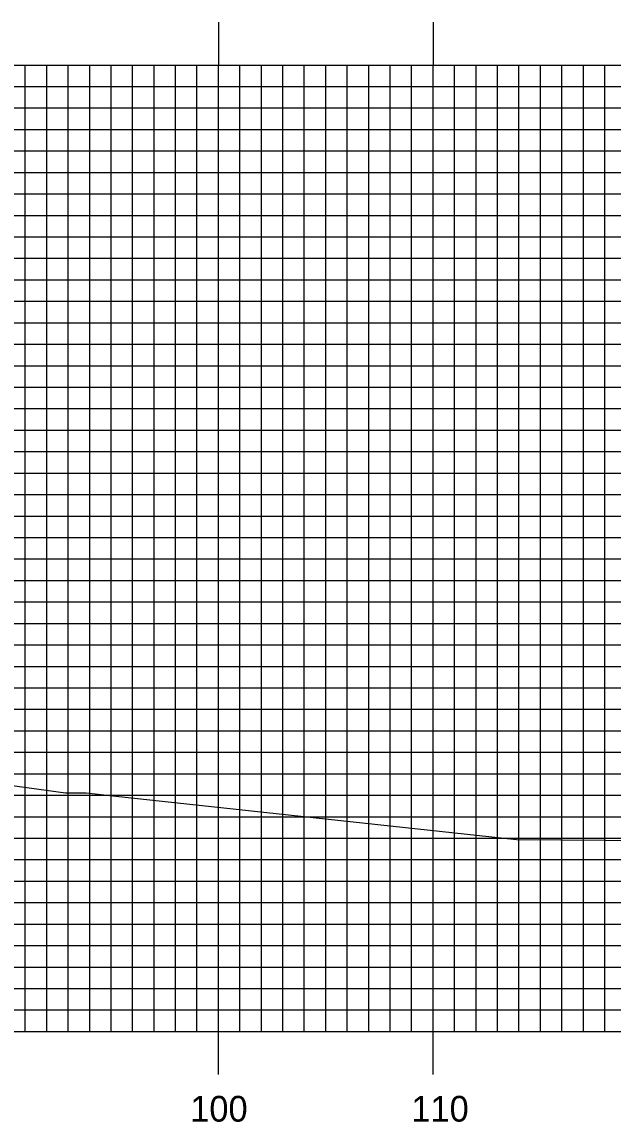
# Model space of a CAD drawing. Extents: x 1785402 to 1785745, y 442591 to 442811.
# Drawn here: x 1785658.4 to 1785685.9, y 442724.4 to 442775.7 of the extents above; entities that cross this region are included whole.
import ezdxf

# ---------------------------------------------------------------- set-up
doc = ezdxf.new("R2010")
doc.units = 0
for name, color, linetype in [('H_V ANNOTATION', 7, 'Continuous'), ('MAJOR', 7, 'Continuous'), ('MINOR', 7, 'Continuous'), ('S_Roadway_Centerline', 7, 'Continuous')]:
    doc.layers.add(name, color=color, linetype=linetype)

msp = doc.modelspace()

# ---------------------------------------------------------------- linework, layer by layer
at = {"layer": 'MAJOR'}
for p, q in [((1785667.539, 442775.669), (1785667.539, 442773.665)), ((1785677.539, 442775.669), (1785677.539, 442773.665)), ((1785427.539, 442773.665), (1785707.539, 442773.665)), ((1785427.539, 442773.665), (1785707.539, 442773.665)), ((1785667.539, 442728.665), (1785667.539, 442773.665)), ((1785677.539, 442728.665), (1785677.539, 442773.665)), ((1785427.539, 442768.665), (1785707.539, 442768.665)), ((1785427.539, 442763.665), (1785707.539, 442763.665)), ((1785427.539, 442758.665), (1785707.539, 442758.665)), ((1785427.539, 442753.665), (1785707.539, 442753.665)), ((1785427.539, 442748.665), (1785707.539, 442748.665)), ((1785427.539, 442743.665), (1785707.539, 442743.665)), ((1785427.539, 442738.665), (1785707.539, 442738.665)), ((1785427.539, 442733.665), (1785707.539, 442733.665)), ((1785427.539, 442728.665), (1785707.539, 442728.665)), ((1785427.539, 442728.665), (1785707.539, 442728.665)), ((1785667.539, 442726.661), (1785667.539, 442728.665)), ((1785677.539, 442726.661), (1785677.539, 442728.665))]:
    msp.add_line(p, q, dxfattribs=at)
at = {"layer": 'MINOR'}
for p, q in [((1785658.539, 442728.665), (1785658.539, 442773.665)), ((1785659.539, 442728.665), (1785659.539, 442773.665)), ((1785660.539, 442728.665), (1785660.539, 442773.665)), ((1785661.539, 442728.665), (1785661.539, 442773.665)), ((1785662.539, 442728.665), (1785662.539, 442773.665)), ((1785663.539, 442728.665), (1785663.539, 442773.665)), ((1785664.539, 442728.665), (1785664.539, 442773.665)), ((1785665.539, 442728.665), (1785665.539, 442773.665)), ((1785666.539, 442728.665), (1785666.539, 442773.665)), ((1785668.539, 442728.665), (1785668.539, 442773.665)), ((1785669.539, 442728.665), (1785669.539, 442773.665)), ((1785670.539, 442728.665), (1785670.539, 442773.665)), ((1785671.539, 442728.665), (1785671.539, 442773.665)), ((1785672.539, 442728.665), (1785672.539, 442773.665)), ((1785673.539, 442728.665), (1785673.539, 442773.665)), ((1785674.539, 442728.665), (1785674.539, 442773.665)), ((1785675.539, 442728.665), (1785675.539, 442773.665)), ((1785676.539, 442728.665), (1785676.539, 442773.665)), ((1785678.539, 442728.665), (1785678.539, 442773.665)), ((1785679.539, 442728.665), (1785679.539, 442773.665)), ((1785680.539, 442728.665), (1785680.539, 442773.665)), ((1785681.539, 442728.665), (1785681.539, 442773.665)), ((1785682.539, 442728.665), (1785682.539, 442773.665)), ((1785683.539, 442728.665), (1785683.539, 442773.665)), ((1785684.539, 442728.665), (1785684.539, 442773.665)), ((1785685.539, 442728.665), (1785685.539, 442773.665)), ((1785427.539, 442772.665), (1785707.539, 442772.665)), ((1785427.539, 442771.665), (1785707.539, 442771.665)), ((1785427.539, 442770.665), (1785707.539, 442770.665)), ((1785427.539, 442769.665), (1785707.539, 442769.665)), ((1785427.539, 442767.665), (1785707.539, 442767.665)), ((1785427.539, 442766.665), (1785707.539, 442766.665)), ((1785427.539, 442765.665), (1785707.539, 442765.665)), ((1785427.539, 442764.665), (1785707.539, 442764.665)), ((1785427.539, 442762.665), (1785707.539, 442762.665)), ((1785427.539, 442761.665), (1785707.539, 442761.665)), ((1785427.539, 442760.665), (1785707.539, 442760.665)), ((1785427.539, 442759.665), (1785707.539, 442759.665)), ((1785427.539, 442757.665), (1785707.539, 442757.665)), ((1785427.539, 442756.665), (1785707.539, 442756.665)), ((1785427.539, 442755.665), (1785707.539, 442755.665)), ((1785427.539, 442754.665), (1785707.539, 442754.665)), ((1785427.539, 442752.665), (1785707.539, 442752.665)), ((1785427.539, 442751.665), (1785707.539, 442751.665)), ((1785427.539, 442750.665), (1785707.539, 442750.665)), ((1785427.539, 442749.665), (1785707.539, 442749.665)), ((1785427.539, 442747.665), (1785707.539, 442747.665)), ((1785427.539, 442746.665), (1785707.539, 442746.665)), ((1785427.539, 442745.665), (1785707.539, 442745.665)), ((1785427.539, 442744.665), (1785707.539, 442744.665)), ((1785427.539, 442742.665), (1785707.539, 442742.665)), ((1785427.539, 442741.665), (1785707.539, 442741.665)), ((1785427.539, 442740.665), (1785707.539, 442740.665)), ((1785427.539, 442739.665), (1785707.539, 442739.665)), ((1785427.539, 442737.665), (1785707.539, 442737.665)), ((1785427.539, 442736.665), (1785707.539, 442736.665)), ((1785427.539, 442735.665), (1785707.539, 442735.665)), ((1785427.539, 442734.665), (1785707.539, 442734.665)), ((1785427.539, 442732.665), (1785707.539, 442732.665)), ((1785427.539, 442731.665), (1785707.539, 442731.665)), ((1785427.539, 442730.665), (1785707.539, 442730.665)), ((1785427.539, 442729.665), (1785707.539, 442729.665))]:
    msp.add_line(p, q, dxfattribs=at)
at = {"layer": 'S_Roadway_Centerline'}
msp.add_lwpolyline([(1785618.773, 442743.37), (1785637.991, 442741.7), (1785639.632, 442741.606), (1785650.02, 442741.204), (1785660.414, 442739.773), (1785661.375, 442739.775), (1785662.615, 442739.643), (1785681.418, 442737.597), (1785687.643, 442737.554), (1785695.805, 442737.689), (1785701.989, 442736.798), (1785707.539, 442736.423)], dxfattribs=at)

# ---------------------------------------------------------------- texts
at = {"layer": 'H_V ANNOTATION'}
for s, p in [('100', (1785666.222, 442724.465)), ('110', (1785676.522, 442724.465))]:
    msp.add_text(s, height=1.2, dxfattribs=at).set_placement(p)

doc.saveas('drawing.dxf')
